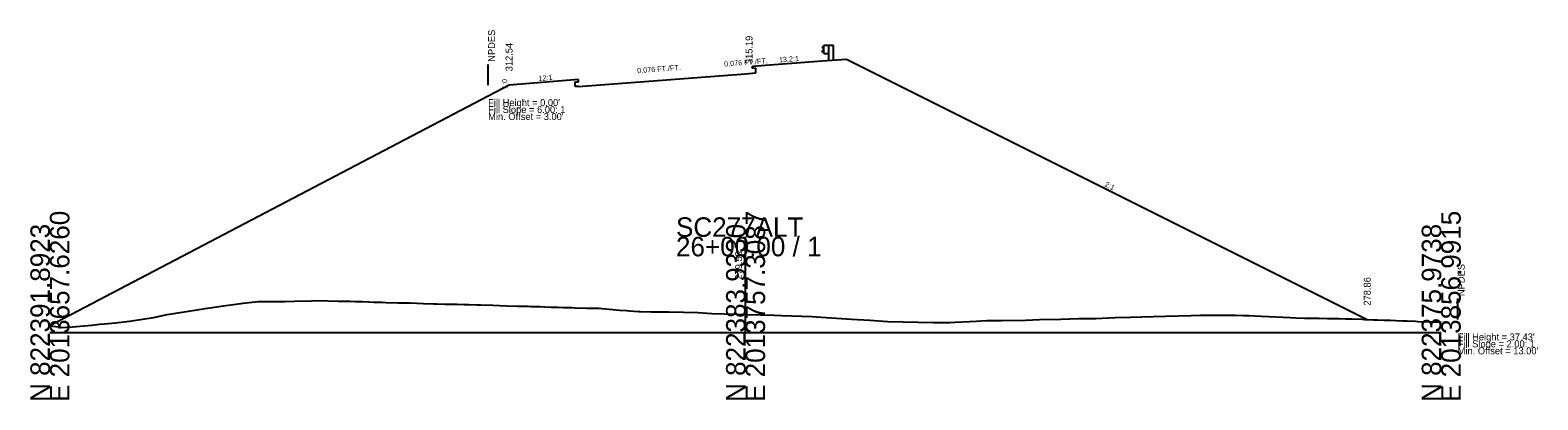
# Model space of a CAD drawing. Extents: x 205929 to 2357175, y -1785700 to 827636.
# Drawn here: x 2017417.3 to 2017634.1, y 824034.6 to 824087.7 of the extents above; entities that cross this region are included whole.
import ezdxf

# ---------------------------------------------------------------- set-up
doc = ezdxf.new("R2010")
doc.units = 0
for name, color, linetype in [('RD_GPK_XS_Cell', 7, 'Continuous'), ('RD_XS_Base', 7, 'Continuous'), ('RD_XS_EarthShd', 7, 'Continuous'), ('RD_XS_ExGround', 7, 'Continuous'), ('RD_XS_GR', 7, 'Continuous'), ('RD_XS_NPDES', 7, 'Continuous'), ('RD_XS_Pave', 7, 'Continuous'), ('RD_XS_TieSlope', 7, 'Continuous'), ('RD_XS_TX_Elev_EX', 7, 'Continuous'), ('RD_XS_TX_Elev_PR', 7, 'Continuous'), ('RD_XS_TX_ShdSlope', 7, 'Continuous'), ('RD_XS_TX_Slope', 7, 'Continuous'), ('RD_XS_TX_Warning', 7, 'Continuous')]:
    doc.layers.add(name, color=color, linetype=linetype)

msp = doc.modelspace()

# ---------------------------------------------------------------- linework, layer by layer
at = {"layer": 'RD_GPK_XS_Cell'}
for p, q in [((2017520.17, 824044.26), (2017520.17, 824058)), ((2017420.17, 824044.26), (2017520.17, 824044.26)), ((2017520.17, 824044.26), (2017620.17, 824044.26))]:
    msp.add_line(p, q, dxfattribs=at)
at = {"layer": 'RD_XS_Base'}
for p, q in [((2017496.17, 824079.63), (2017520.17, 824081.45)), ((2017520.17, 824081.45), (2017521.17, 824081.52))]:
    msp.add_line(p, q, dxfattribs=at)
at = {"layer": 'RD_XS_EarthShd'}
for p, q in [((2017521.17, 824082.52), (2017531.17, 824083.28)), ((2017531.17, 824083.28), (2017534.67, 824083.55)), ((2017496.17, 824080.63), (2017486.17, 824079.79))]:
    msp.add_line(p, q, dxfattribs=at)
at = {"layer": 'RD_XS_ExGround'}
msp.add_line((2017486.17, 824079.79), (2017420.17, 824045.2), dxfattribs=at)
msp.add_lwpolyline([(2017420.17, 824045.2), (2017421.43, 824045.04), (2017422.02, 824044.96), (2017422.61, 824044.99), (2017423.41, 824045.05), (2017426.2, 824045.32), (2017427.32, 824045.43), (2017428.04, 824045.49), (2017428.55, 824045.54), (2017429.62, 824045.63), (2017431.59, 824045.86), (2017435.07, 824046.42), (2017437.04, 824046.81), (2017440.09, 824047.33), (2017442.49, 824047.7), (2017445.11, 824048.08), (2017447.94, 824048.46), (2017450.12, 824048.68), (2017453.06, 824048.68), (2017453.94, 824048.71), (2017455.33, 824048.74), (2017457.76, 824048.81), (2017458.58, 824048.84), (2017460.1, 824048.8), (2017461.62, 824048.77), (2017462.08, 824048.75), (2017463.33, 824048.73), (2017464.04, 824048.71), (2017465.04, 824048.68), (2017466.02, 824048.65), (2017466.75, 824048.62), (2017468, 824048.59), (2017468.47, 824048.58), (2017470.17, 824048.53), (2017471.53, 824048.5), (2017471.94, 824048.49), (2017473.86, 824048.43), (2017475.3, 824048.39), (2017475.81, 824048.38), (2017476.99, 824048.33), (2017477.73, 824048.31), (2017478.69, 824048.3), (2017479.68, 824048.27), (2017480.4, 824048.25), (2017481.61, 824048.21), (2017482.11, 824048.2), (2017483.82, 824048.16), (2017485.79, 824048.1), (2017487.41, 824048.05), (2017488.91, 824048.01), (2017489.37, 824048), (2017490.6, 824047.96), (2017491.31, 824047.94), (2017492.29, 824047.91), (2017493.24, 824047.88), (2017493.99, 824047.85), (2017495.19, 824047.82), (2017495.69, 824047.81), (2017497.37, 824047.76), (2017499.07, 824047.72), (2017500.55, 824047.59), (2017501.08, 824047.55), (2017502.04, 824047.48), (2017503.07, 824047.39), (2017503.51, 824047.36), (2017504.77, 824047.26), (2017505.08, 824047.26), (2017506.61, 824047.24), (2017507.58, 824047.24), (2017508.25, 824047.23), (2017508.75, 824047.23), (2017509.12, 824047.22), (2017513.36, 824047.1), (2017515.33, 824047), (2017518.81, 824046.87), (2017520.34, 824046.83), (2017524.26, 824046.75), (2017525.36, 824046.69), (2017529.71, 824046.53), (2017530.38, 824046.5), (2017535.39, 824046.16), (2017538.05, 824046), (2017540.61, 824045.85), (2017547.19, 824045.66), (2017547.83, 824045.66), (2017548.66, 824045.68), (2017549.53, 824045.69), (2017550.3, 824045.73), (2017552.37, 824045.82), (2017553.38, 824045.88), (2017553.98, 824045.9), (2017554.86, 824045.95), (2017556.97, 824045.99), (2017560.47, 824046.04), (2017562.42, 824046.11), (2017565.49, 824046.18), (2017568.1, 824046.26), (2017570.5, 824046.28), (2017573.32, 824046.38), (2017575.52, 824046.45), (2017578.77, 824046.54), (2017580.54, 824046.57), (2017584.22, 824046.71), (2017585.55, 824046.72), (2017589.67, 824046.75), (2017590.57, 824046.74), (2017591.75, 824046.7), (2017592.08, 824046.69), (2017592.56, 824046.67), (2017593.34, 824046.63), (2017598.48, 824046.4), (2017599.27, 824046.37), (2017600.53, 824046.33), (2017601.99, 824046.31), (2017602.61, 824046.3), (2017603.76, 824046.27), (2017605.14, 824046.24), (2017605.52, 824046.24), (2017606.41, 824046.22), (2017607.33, 824046.19), (2017608.83, 824046.14), (2017609.16, 824046.13), (2017610.44, 824046.08), (2017610.99, 824046.06), (2017612.04, 824046.03), (2017612.81, 824046), (2017613.65, 824045.97), (2017614.64, 824045.94), (2017615.26, 824045.91), (2017616.47, 824045.87), (2017616.87, 824045.85), (2017618.48, 824045.8), (2017619.78, 824045.76), (2017620.17, 824045.75)], dxfattribs=at)
at = {"layer": 'RD_XS_GR'}
for p, q in [((2017531.44, 824085.46), (2017531.17, 824085.26)), ((2017531.17, 824085.26), (2017531.17, 824085.21)), ((2017531.17, 824085.21), (2017531.44, 824085.01)), ((2017531.44, 824084.36), (2017531.44, 824085.53)), ((2017531.44, 824085.53), (2017532.11, 824085.53)), ((2017532.11, 824085.53), (2017532.11, 824083.35)), ((2017532.11, 824085.53), (2017532.78, 824085.53)), ((2017532.78, 824085.53), (2017532.78, 824083.4)), ((2017531.17, 824084.69), (2017531.44, 824084.89)), ((2017531.17, 824084.64), (2017531.17, 824084.69)), ((2017531.44, 824084.44), (2017531.17, 824084.64)), ((2017531.44, 824084.36), (2017532.11, 824084.36))]:
    msp.add_line(p, q, dxfattribs=at)
at = {"layer": 'RD_XS_NPDES'}
for p, q in [((2017483.17, 824079.79), (2017483.17, 824082.79)), ((2017622.54, 824046.11), (2017622.54, 824049.11))]:
    msp.add_line(p, q, dxfattribs=at)
at = {"layer": 'RD_XS_Pave'}
for p, q in [((2017496.17, 824080.3), (2017496.17, 824080.63)), ((2017521.17, 824082.19), (2017521.17, 824082.52)), ((2017521.67, 824082.23), (2017521.17, 824082.19)), ((2017521.17, 824081.52), (2017521.67, 824081.56)), ((2017521.67, 824081.56), (2017521.67, 824082.23)), ((2017495.67, 824080.26), (2017496.17, 824080.3)), ((2017495.67, 824079.59), (2017495.67, 824080.26)), ((2017496.17, 824079.63), (2017495.67, 824079.59))]:
    msp.add_line(p, q, dxfattribs=at)
at = {"layer": 'RD_XS_TieSlope'}
msp.add_line((2017534.67, 824083.55), (2017609.54, 824046.11), dxfattribs=at)

# ---------------------------------------------------------------- texts
at = {"layer": 'RD_GPK_XS_Cell'}
for s, p in [('E 2013657.6260', (2017422.97, 824034.26)), ('E 2013757.3087', (2017522.97, 824034.26)), ('E 2013856.9915', (2017622.97, 824034.26)), ('N 822391.8923', (2017420.17, 824034.26)), ('N 822383.9330', (2017520.17, 824034.26)), ('N 822375.9738', (2017620.17, 824034.26))]:
    msp.add_text(s, height=2.8, rotation=90, dxfattribs=at).set_placement(p)
for s, p in [('SC277ALT', (2017510.17, 824058)), ('26+00.00 / 1', (2017510.17, 824055.2))]:
    msp.add_text(s, height=2.8, dxfattribs=at).set_placement(p)
at = {"layer": 'RD_XS_TX_Elev_EX'}
msp.add_text('279.58', height=1, rotation=90, dxfattribs=at).set_placement((2017519.67, 824051.84))
at = {"layer": 'RD_XS_TX_Elev_PR'}
for s, p in [('312.54', (2017486.67, 824081.79)), (' 315.19', (2017521.17, 824082.45)), ('278.86', (2017610.04, 824048.11))]:
    msp.add_text(s, height=1, rotation=90, dxfattribs=at).set_placement(p)
at = {"layer": 'RD_XS_TX_ShdSlope'}
for s, rotation, p in [('13.2:1', 4.3347, (2017525, 824083.06)), ('12:1', 4.7636, (2017490.44, 824080.4))]:
    msp.add_text(s, height=0.75, rotation=rotation, dxfattribs=at).set_placement(p)
at = {"layer": 'RD_XS_TX_Slope'}
for s, rotation, p in [('0.076 FT./FT.', 4.3347, (2017517.12, 824082.47)), ('1:0', 90, (2017485.92, 824079.25)), ('0.076 FT./FT.', 4.3347, (2017504.62, 824081.52)), ('2:1', 333.4349, (2017571.71, 824065.31))]:
    msp.add_text(s, height=0.75, rotation=rotation, dxfattribs=at).set_placement(p)
at = {"layer": 'RD_XS_TX_Warning'}
for p in [(2017484.17, 824082.79), (2017623.54, 824049.11)]:
    msp.add_text(' NPDES', height=1, rotation=90, dxfattribs=at).set_placement(p)
for s, p in [("Fill Height = 0.00' ", (2017483.17, 824076.79)), ('Fill Slope = 6.00: 1', (2017483.17, 824075.79)), ("Min. Offset = 3.00' ", (2017483.17, 824074.79)), ("Fill Height = 37.43' ", (2017622.54, 824043.11)), ('Fill Slope = 2.00: 1', (2017622.54, 824042.11)), ("Min. Offset = 13.00' ", (2017622.54, 824041.11))]:
    msp.add_text(s, height=1, dxfattribs=at).set_placement(p)

doc.saveas('drawing.dxf')
